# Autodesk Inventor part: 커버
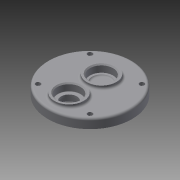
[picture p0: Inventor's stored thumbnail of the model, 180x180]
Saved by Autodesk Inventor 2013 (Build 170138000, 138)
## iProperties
Created: 2015-07
Part Number: 커버
Material: 일반
Document SubType Name: Modeling
Designer: user
Density: 1 g/cm^3
Author: user
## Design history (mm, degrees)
sketch "스케치1"
  geometry: C1 r 40 at (0, 0); 1 further point
  constraints: 1 centre point, 1 coincident
  dimensions: "d0" = 80 diameter of C1
extrude "돌출1" new body sketch "스케치1" distance "d1" = 9; taper "d2" = 0 deg
sketch "스케치2"
  geometry: L1 (-38.681, 0)-(40, 0); L2 (0, 0)-(0, 11); L3 (0, 0)-(0, -20); C1 r 14 at (0, 11); C2 r 14 at (0, -20)
  constraints: 6 end point, 2 centre point, 2 coincident, 1 collinear, 1 horizontal, 1 horizontal alignment, 1 perpendicular, 1 point on line, 1 other
  dimensions: "d3" = 11 distance of L2.start L2.end; "d4" = 20 distance of L2.start L3.end; "d5" = 28 diameter of C1; "d6" = 28 diameter of C2
extrude "돌출2" join sketch "스케치2" distance "d7" = 3; taper "d8" = 0 deg
sketch "스케치3"
  geometry: C1 r 14 at (0, 0) reference; C2 r 11 at (0, 0); 1 further point
  constraints: 1 centre point, 1 coincident
  dimensions: "d9" = 22 diameter of C2
extrude "돌출3" cut sketch "스케치3" distance "d10" = 7; taper "d11" = 0 deg
sketch "스케치4"
  geometry: C1 r 9 at (0, 0); 2 further points
  constraints: 1 centre point, 1 coincident, 1 vertical alignment
  dimensions: "d12" = 18 diameter of C1
extrude "돌출4" cut sketch "스케치4" distance "d13" = 1; taper "d14" = 0 deg
fillet "모깎기1" dims "d15" = 2
fillet "모깎기2" dims "d16" = 0.3
chamfer "모따기1" distance "d17" = 1; stored, may be unused: second distance "d18" = 2, angle "d19" = 45 deg
sketch "스케치5"
  geometry: C1 r 14 at (0, 0) reference; C2 r 11 at (0, 0); 1 further point
  constraints: 1 centre point, 1 coincident
  dimensions: "d20" = 22 diameter of C2
extrude "돌출5" cut sketch "스케치5" distance "d21" = 7; taper "d22" = 0 deg
sketch "스케치6"
  geometry: C1 r 11 at (0, 0) reference; C2 r 7.5 at (0, 0); 1 further point
  constraints: 1 centre point, 1 coincident
  dimensions: "d23" = 15 diameter of C2
extrude "돌출6" cut sketch "스케치6" distance "d24" = 2; taper "d25" = 0 deg
sketch "스케치8"
  geometry: L1 (0, 0)-(0, -20); C1 r 40 at (0, 0) reference; C2 r 15 at (0, -20)
  constraints: 2 end point, 1 centre point, 1 coincident, 1 vertical
  dimensions: "d28" = 20 distance of L1.start L1.end; "d29" = 30 diameter of C2
extrude "돌출7" join sketch "스케치8" distance "d30" = 4; taper "d31" = 0 deg
sketch "스케치9"
  geometry: C1 r 15 at (0, 0) reference; C2 r 11 at (0, 0); 1 further point
  constraints: 1 centre point, 1 coincident
  dimensions: "d32" = 22 diameter of C2
extrude "돌출8" cut sketch "스케치9" distance "d33" = 7; taper "d34" = 0 deg
fillet "모깎기3" dims "d35" = 0.3
fillet "모깎기4" dims "d36" = 0.3
chamfer "모따기2" distance "d37" = 1; stored, may be unused: second distance "d38" = 2, angle "d39" = 45 deg
chamfer "모따기3" distance "d40" = 1; stored, may be unused: second distance "d41" = 2, angle "d42" = 45 deg
fillet "모깎기5" dims "d43" = 2
fillet "모깎기6" dims "d44" = 2
fillet "모깎기7" dims "d45" = 2
fillet "모깎기8" dims "d46" = 2
sketch "스케치10"
  geometry: L1 (0, 0)-(0, 35); L2 (0, 0)-(24.749, 24.749); C1 r 40 at (0, 0) reference; A1 r 35 centre (0, 0) between (0, 35) and (24.749, 24.749); 4 further points
  constraints: 4 end point, 2 coincident, 2 point on circle, 1 centre point, 1 vertical, 5 other
  dimensions: "d47" = 70 diameter of A1; "d48" = 45 deg angle of L2 L1; "d52" = 360 deg dimension on L1.start point (24.749, 24.749) (derived)
hole "구멍1" sketch "스케치10" at (24.749, 24.749), (-24.749, 24.749), (-24.749, -24.749), (24.749, -24.749) diameter "d54" = 4.5; stored, may be unused: countersink angle "d58" = 90 deg, drill point angle "d60" = 118 deg; dims "d55" = 6, "d56" = 8, "d57" = 4.4, "d59" = 10
node "솔리드1"
